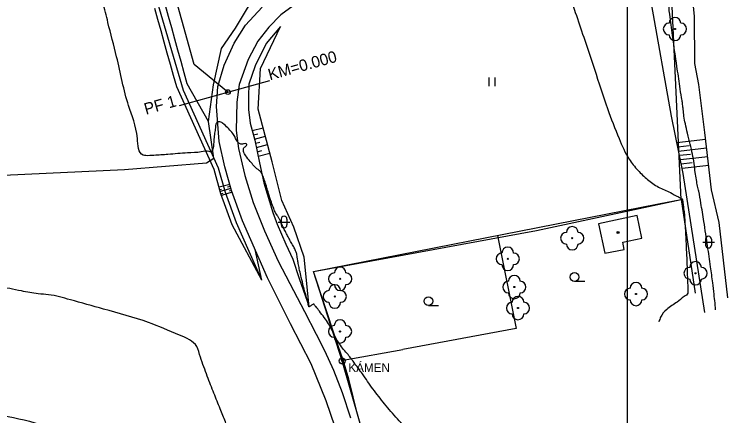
# Model space of a CAD drawing. Extents: x -478102 to -473059, y -1117705 to -1114104.
# Drawn here: x -476287.7 to -476165.9, y -1117155.6 to -1117086.7 of the extents above; entities that cross this region are included whole.
import ezdxf

# ---------------------------------------------------------------- set-up
doc = ezdxf.new("R2010")
doc.units = 0
for name, color, linetype in [('BodoveZnackySloupy', 7, 'Continuous'), ('Budovy', 7, 'Continuous'), ('cestn___p____kop', 7, 'Continuous'), ('cestn___p____kop_n__vrh', 7, 'Continuous'), ('cesty', 7, 'Continuous'), ('DESQ_pomoc', 7, 'Continuous'), ('HladinaVodnihoToku', 7, 'Continuous'), ('ObPÚ', 7, 'Continuous'), ('Ploty', 7, 'Continuous'), ('POLYGONY_SITUACE_PF', 7, 'Continuous'), ('POLYGONY_SITUACE_PF_POPISY', 7, 'Continuous'), ('POLYGONY_SITUACE_PO', 7, 'Continuous'), ('PopisnaZnackaVyhybka', 7, 'Continuous'), ('PopisneZnackyKultura', 7, 'Continuous'), ('PopisObjektu', 7, 'Continuous'), ('RozhraniKultur', 7, 'Continuous'), ('RozhraniVozovky', 7, 'Continuous'), ('Teren_HranaSvahu', 7, 'Continuous'), ('Teren_PataSvahu', 7, 'Continuous'), ('Vrstevnice_hlavni', 7, 'Continuous'), ('Vrstevnice_vedlejsi', 7, 'Continuous'), ('VstupNaPozemek', 7, 'Continuous'), ('VyskoveSrafy', 7, 'Continuous'), ('ZnackyStromu', 7, 'Continuous')]:
    doc.layers.add(name, color=color, linetype=linetype)

msp = doc.modelspace()

# ---------------------------------------------------------------- linework, layer by layer
at = {"layer": 'BodoveZnackySloupy'}
for radius in [0.5, 0.1]:
    msp.add_circle((-476231.32, -1117146.23), radius, dxfattribs=at)
at = {"layer": 'Budovy'}
msp.add_lwpolyline([(-476179.82, -1117125.147), (-476180.599, -1117121.234), (-476187.275, -1117122.701), (-476186.207, -1117127.742), (-476182.873, -1117127.103), (-476183.091, -1117125.822)], close=True, dxfattribs=at)
at = {"layer": 'cestn___p____kop'}
for p, q in [((-476250.632, -1117115.923), (-476252.471, -1117116.401)), ((-476252.362, -1117116.788), (-476252.026, -1117116.7)), ((-476250.433, -1117116.627), (-476252.264, -1117117.134)), ((-476250.534, -1117116.268), (-476250.996, -1117116.397)), ((-476250.345, -1117116.938), (-476250.73, -1117117.053)), ((-476252.157, -1117117.511), (-476251.788, -1117117.406)), ((-476250.225, -1117117.27), (-476252.044, -1117117.829))]:
    msp.add_line(p, q, dxfattribs=at)
at = {"layer": 'cestn___p____kop_n__vrh'}
msp.add_lwpolyline([(-476182.335, -1117180.282), (-476602.335, -1117180.282), (-476602.335, -1116586.282), (-476182.335, -1116586.282)], close=True, dxfattribs=at)
at = {"layer": 'cesty'}
for p, q in [((-476258.59, -1117099.803), (-476264.043, -1117081.125)), ((-476261.133, -1117087.098), (-476261.667, -1117085.17)), ((-476260.599, -1117089.025), (-476261.133, -1117087.098)), ((-476260.064, -1117090.952), (-476260.599, -1117089.025)), ((-476259.53, -1117092.88), (-476260.064, -1117090.952)), ((-476258.996, -1117094.807), (-476259.53, -1117092.88)), ((-476258.461, -1117096.734), (-476258.996, -1117094.807)), ((-476257.927, -1117098.661), (-476258.461, -1117096.734)), ((-476254.26, -1117105.118), (-476257.927, -1117098.661))]:
    msp.add_line(p, q, dxfattribs=at)
for points in [[(-476262.981, -1117087.61), (-476263.521, -1117085.684)], [(-476262.442, -1117089.536), (-476262.981, -1117087.61)], [(-476261.903, -1117091.462), (-476262.442, -1117089.536)], [(-476261.364, -1117093.388), (-476261.903, -1117091.462)], [(-476260.822, -1117095.313), (-476261.364, -1117093.388)], [(-476260.281, -1117097.239), (-476260.822, -1117095.313)], [(-476259.74, -1117099.164), (-476260.281, -1117097.239)], [(-476259.74, -1117099.164), (-476259.74, -1117099.164)]]:
    msp.add_lwpolyline(points, dxfattribs=at)
at = {"layer": 'DESQ_pomoc'}
msp.add_line((-476245.113, -1117132.379), (-476246.288, -1117127.059), dxfattribs=at)
at = {"layer": 'HladinaVodnihoToku'}
msp.add_lwpolyline([(-476165.052, -1117135.383), (-476166.552, -1117122.432), (-476167.831, -1117116.835), (-476168.995, -1117106.978), (-476170.029, -1117098.738), (-476170.701, -1117095.145), (-476170.746, -1117087.056), (-476171.949, -1117074.832), (-476173.391, -1117070.652), (-476173.059, -1117068.741), (-476173.366, -1117065.264), (-476174.142, -1117057.395), (-476175.337, -1117045.193), (-476176.15, -1117036.518), (-476177.362, -1117031.476), (-476176.964, -1117029.141), (-476177.777, -1117025.659), (-476180.222, -1117017.465), (-476181.969, -1117010.204)], dxfattribs=at)
at = {"layer": 'ObPÚ'}
msp.add_lwpolyline([(-476159.5, -1117192.77), (-476224.13, -1117203.13), (-476225.41, -1117191.08), (-476226.67, -1117162.34), (-476231.32, -1117146.23), (-476236.27, -1117130.89), (-476197.93, -1117123.85), (-476173.05, -1117118.52), (-476175.07, -1117075.48), (-476185.89, -1117036.74), (-476189.59, -1117026.33), (-476192, -1117018.92), (-476203.93, -1116985.93)], dxfattribs=at)
at = {"layer": 'Ploty'}
for p, q in [((-476173.05, -1117118.52), (-476170.664, -1117134.589)), ((-476204.648, -1117124.689), (-476201.416, -1117140.657)), ((-476201.416, -1117140.657), (-476220.878, -1117144.236)), ((-476231.16, -1117146.08), (-476220.878, -1117144.236))]:
    msp.add_line(p, q, dxfattribs=at)
for points in [[(-476236.27, -1117130.89), (-476176.96, -1117119.26), (-476173.05, -1117118.52)], [(-476232.38, -1117142.5), (-476236.27, -1117130.89)], [(-476230.16, -1117149.36), (-476231.16, -1117146.08)]]:
    msp.add_lwpolyline(points, dxfattribs=at)
at = {"layer": 'POLYGONY_SITUACE_PF'}
msp.add_lwpolyline([(-476259.271, -1117102.36), (-476250.954, -1117100.054), (-476243.727, -1117098.051)], dxfattribs=at)
at = {"layer": 'POLYGONY_SITUACE_PO'}
msp.add_lwpolyline([(-476250.954, -1117100.054), (-476256.772, -1117095.342), (-476265.518, -1117063.797), (-476268.51, -1117056.912), (-476273.282, -1117051.116), (-476279.465, -1117046.859), (-476286.581, -1117044.469), (-476294.08, -1117044.131), (-476301.427, -1117045.065)], dxfattribs=at)
msp.add_circle((-476250.954, -1117100.054), 0.395, dxfattribs=at)
at = {"layer": 'PopisnaZnackaVyhybka'}
for radius in [0.18, 0.0797]:
    msp.add_circle((-476183.909, -1117124.176), radius, dxfattribs=at)
at = {"layer": 'PopisneZnackyKultura'}
for p, q in [((-476206.051, -1117099.044), (-476206.051, -1117097.544)), ((-476205.051, -1117099.044), (-476205.051, -1117097.544)), ((-476241.815, -1117121.87), (-476241.815, -1117122.87)), ((-476240.815, -1117121.87), (-476240.815, -1117122.87)), ((-476242.315, -1117122.37), (-476240.315, -1117122.37)), ((-476168.864, -1117125.331), (-476168.864, -1117126.331)), ((-476167.864, -1117125.331), (-476167.864, -1117126.331)), ((-476169.364, -1117125.831), (-476167.364, -1117125.831)), ((-476191.384, -1117132.551), (-476189.624, -1117132.551)), ((-476216.498, -1117136.728), (-476214.738, -1117136.728))]:
    msp.add_line(p, q, dxfattribs=at)
for centre in [(-476191.384, -1117131.811), (-476216.498, -1117135.968)]:
    msp.add_circle(centre, 0.75, dxfattribs=at)
for centre, start, end in [((-476241.307, -1117121.862), 0, 180), ((-476241.307, -1117122.862), 180, 0), ((-476168.356, -1117125.324), 0, 180), ((-476168.356, -1117126.324), 180, 0)]:
    msp.add_arc(centre, 0.5, start, end, dxfattribs=at)
at = {"layer": 'RozhraniKultur'}
msp.add_lwpolyline([(-476326.155, -1117118.092), (-476289.536, -1117114.347), (-476268.698, -1117113.377), (-476254.616, -1117112.232), (-476253.368, -1117111.396), (-476254.26, -1117105.118), (-476253.444, -1117098.834), (-476252.052, -1117092.56), (-476249.674, -1117089.102), (-476247.41, -1117085.365), (-476243.552, -1117082.341), (-476239.642, -1117080.005), (-476234.251, -1117077.288), (-476223.428, -1117073.653), (-476215.212, -1117070.499), (-476211.753, -1117068.101), (-476207.257, -1117063.687), (-476203.922, -1117059.007), (-476201.245, -1117053.431), (-476199.908, -1117046.384), (-476198.206, -1117031.932)], dxfattribs=at)
at = {"layer": 'RozhraniVozovky'}
for points in [[(-476232.539, -1117157.584), (-476234.044, -1117153.045), (-476236.653, -1117146.701), (-476240.196, -1117139.821), (-476244.137, -1117131.967), (-476248.439, -1117122.151), (-476250.337, -1117116.965), (-476251.495, -1117112.871), (-476252.444, -1117108.527), (-476252.919, -1117102.558), (-476252.654, -1117099.075), (-476251.576, -1117095.426), (-476249.859, -1117091.68), (-476247.93, -1117088.545), (-476245.077, -1117085.472)], [(-476239.761, -1117085.24), (-476241.85, -1117086.802), (-476243.905, -1117088.925), (-476245.795, -1117091.335), (-476247.443, -1117094.453), (-476248.993, -1117098.742), (-476249.417, -1117101.776), (-476249.514, -1117106.658), (-476249.129, -1117109.728), (-476248.034, -1117114.356), (-476246.613, -1117119.033), (-476244.684, -1117123.906), (-476242.288, -1117129.115), (-476240.331, -1117132.949), (-476237.801, -1117137.737), (-476235.804, -1117141.64), (-476234.344, -1117144.407), (-476232.794, -1117147.784), (-476231.339, -1117151.616), (-476229.905, -1117155.995)], [(-476245.113, -1117132.379), (-476250.203, -1117122.86), (-476252.146, -1117117.551), (-476253.339, -1117113.333), (-476259.74, -1117099.164), (-476259.74, -1117099.164), (-476259.74, -1117099.164)], [(-476245.113, -1117132.379), (-476249.471, -1117122.532), (-476251.384, -1117117.304), (-476252.563, -1117113.138), (-476252.563, -1117113.138), (-476258.59, -1117099.803), (-476258.59, -1117099.803)], [(-476245.113, -1117132.379), (-476250.203, -1117122.86), (-476252.146, -1117117.551), (-476253.339, -1117113.333)], [(-476245.113, -1117132.379), (-476249.471, -1117122.532), (-476251.384, -1117117.304), (-476252.563, -1117113.138)]]:
    msp.add_lwpolyline(points, dxfattribs=at)
at = {"layer": 'Teren_HranaSvahu'}
for p, q in [((-476174.722, -1117104.178), (-476178.08, -1117085.22)), ((-476172.711, -1117114.033), (-476174.722, -1117104.178)), ((-476168.996, -1117137.921), (-476172.711, -1117114.033))]:
    msp.add_line(p, q, dxfattribs=at)
msp.add_lwpolyline([(-476241.907, -1117088.771), (-476244.381, -1117091.697), (-476246.266, -1117095.564), (-476247.357, -1117098.679), (-476247.405, -1117100.757), (-476247.403, -1117103.059), (-476247.148, -1117105.38), (-476246.321, -1117108.303), (-476245.519, -1117112.214), (-476244.755, -1117115.631), (-476243.212, -1117120.707), (-476242.462, -1117122.744), (-476241.012, -1117126.146), (-476239.788, -1117128.744), (-476238.72, -1117132.057), (-476237, -1117136.918)], dxfattribs=at)
at = {"layer": 'Teren_PataSvahu'}
msp.add_lwpolyline([(-476237, -1117136.918), (-476237.832, -1117128.393), (-476239.617, -1117123.274), (-476241.661, -1117118.667), (-476243.331, -1117112.033), (-476245.747, -1117102.973), (-476245.359, -1117095.988), (-476241.907, -1117088.771)], dxfattribs=at)
at = {"layer": 'Vrstevnice_hlavni'}
for points in [[(-476249.493, -1117108.392), (-476249.775, -1117107.699), (-476250.264, -1117106.97), (-476250.958, -1117106.207), (-476251.857, -1117105.408), (-476252.513, -1117105.14), (-476252.925, -1117105.402), (-476253.095, -1117106.195), (-476253.235, -1117107.1), (-476253.347, -1117108.118), (-476253.43, -1117109.248), (-476253.596, -1117109.985), (-476253.847, -1117110.328), (-476254.181, -1117110.278), (-476255.528, -1117110.336), (-476257.887, -1117110.502), (-476261.259, -1117110.776), (-476263.654, -1117110.928), (-476265.074, -1117110.957), (-476265.519, -1117110.863), (-476266.5, -1117108.002), (-476268.017, -1117102.375), (-476270.071, -1117093.98), (-476271.569, -1117088.098), (-476272.511, -1117084.73), (-476272.897, -1117083.874), (-476273.181, -1117083.184), (-476273.365, -1117082.66), (-476273.447, -1117082.301), (-476273.665, -1117081.937), (-476274.021, -1117081.569), (-476274.513, -1117081.196), (-476274.898, -1117080.887), (-476275.174, -1117080.644), (-476275.342, -1117080.466), (-476275.953, -1117078.624), (-476277.006, -1117075.118), (-476278.503, -1117069.948), (-476279.866, -1117064.113), (-476281.094, -1117057.612), (-476282.188, -1117050.447), (-476282.997, -1117045.306), (-476283.52, -1117042.188), (-476283.758, -1117041.094), (-476283.99, -1117040.218), (-476284.216, -1117039.561), (-476284.654, -1117038.684)], [(-476206.652, -1117178.906), (-476206.912, -1117178.348), (-476209.341, -1117173.725), (-476211.536, -1117169.856), (-476213.496, -1117166.739), (-476215.223, -1117164.376), (-476216.372, -1117162.765), (-476216.944, -1117161.906), (-476216.939, -1117161.798), (-476216.948, -1117161.695), (-476216.97, -1117161.597), (-476217.006, -1117161.504), (-476217.035, -1117161.434), (-476217.055, -1117161.387), (-476217.068, -1117161.364), (-476217.869, -1117160.487), (-476219.458, -1117158.755), (-476221.836, -1117156.168), (-476224.025, -1117153.59), (-476226.026, -1117151.021), (-476227.839, -1117148.461), (-476229.316, -1117146.439), (-476230.458, -1117144.956), (-476231.265, -1117144.011), (-476231.967, -1117143.022), (-476232.564, -1117141.99), (-476233.057, -1117140.915), (-476233.666, -1117139.839), (-476234.391, -1117138.762), (-476235.231, -1117137.684), (-476235.806, -1117136.941), (-476236.117, -1117136.531), (-476236.162, -1117136.455), (-476236.279, -1117136.467), (-476236.468, -1117136.566), (-476236.728, -1117136.753), (-476236.903, -1117136.876), (-476236.994, -1117136.936), (-476237.001, -1117136.931), (-476237.008, -1117136.923), (-476237.014, -1117136.912), (-476237.021, -1117136.898), (-476237.036, -1117136.855), (-476237.059, -1117136.783), (-476237.089, -1117136.682), (-476237.266, -1117136.022), (-476237.588, -1117134.805), (-476238.057, -1117133.03), (-476238.423, -1117131.552), (-476238.688, -1117130.371), (-476238.85, -1117129.488), (-476238.979, -1117128.769), (-476239.073, -1117128.213), (-476239.134, -1117127.822), (-476239.32, -1117127.303), (-476239.632, -1117126.656), (-476240.07, -1117125.882), (-476240.487, -1117125.12), (-476240.885, -1117124.371), (-476241.262, -1117123.634), (-476241.579, -1117122.995), (-476241.836, -1117122.453), (-476242.033, -1117122.009), (-476242.251, -1117121.588), (-476242.49, -1117121.19), (-476242.749, -1117120.815), (-476243.08, -1117120.066), (-476243.481, -1117118.944), (-476243.953, -1117117.449), (-476244.291, -1117116.381), (-476244.494, -1117115.74), (-476244.561, -1117115.526), (-476244.665, -1117115.217), (-476244.806, -1117114.813), (-476244.984, -1117114.313), (-476245.236, -1117113.882), (-476245.562, -1117113.52), (-476245.962, -1117113.226), (-476246.483, -1117112.711), (-476247.125, -1117111.974), (-476247.888, -1117111.015), (-476248.249, -1117110.238), (-476248.209, -1117109.642), (-476247.766, -1117109.227), (-476247.681, -1117108.981), (-476247.952, -1117108.903), (-476248.581, -1117108.994), (-476249.094, -1117108.824), (-476249.493, -1117108.392)]]:
    msp.add_spline(points, degree=3, dxfattribs=at)
at = {"layer": 'Vrstevnice_vedlejsi'}
for points in [[(-476361.641, -1116910.017), (-476360.991, -1116911.137), (-476360.552, -1116912.67), (-476360.323, -1116914.616), (-476360.306, -1116916.973), (-476360.308, -1116918.585), (-476360.329, -1116919.449), (-476360.369, -1116919.567), (-476360.386, -1116919.663), (-476360.38, -1116919.738), (-476360.35, -1116919.79), (-476360.486, -1116921.699), (-476360.787, -1116925.464), (-476361.254, -1116931.086), (-476361.67, -1116935.051), (-476362.037, -1116937.36), (-476362.353, -1116938.012), (-476362.549, -1116938.736), (-476362.623, -1116939.532), (-476362.576, -1116940.398), (-476362.264, -1116942.869), (-476361.686, -1116946.945), (-476360.843, -1116952.626), (-476360.093, -1116958.73), (-476359.435, -1116965.256), (-476358.871, -1116972.204), (-476358.36, -1116977.092), (-476357.904, -1116979.919), (-476357.501, -1116980.685), (-476356.57, -1116984.99), (-476355.11, -1116992.835), (-476353.122, -1117004.219), (-476351.571, -1117012.905), (-476350.455, -1117018.893), (-476349.776, -1117022.183), (-476349.504, -1117027.698), (-476349.639, -1117035.437), (-476350.182, -1117045.4), (-476350.307, -1117053.191), (-476350.012, -1117058.811), (-476349.298, -1117062.259), (-476350.091, -1117065.67), (-476352.39, -1117069.042), (-476356.195, -1117072.377), (-476359.92, -1117076.705), (-476363.566, -1117082.026), (-476367.131, -1117088.339), (-476371.33, -1117094.641), (-476376.164, -1117100.933), (-476381.631, -1117107.213), (-476386.474, -1117112.181), (-476390.692, -1117115.834), (-476394.286, -1117118.174), (-476397.491, -1117120.393), (-476400.306, -1117122.492), (-476402.732, -1117124.472), (-476402.928, -1117127.738), (-476400.894, -1117132.291), (-476396.631, -1117138.131), (-476389.647, -1117141.585), (-476379.944, -1117142.653), (-476367.521, -1117141.334), (-476355.525, -1117141.406), (-476343.957, -1117142.868), (-476332.816, -1117145.722), (-476324.482, -1117147.814), (-476318.952, -1117149.144), (-476316.229, -1117149.714), (-476310.745, -1117150.91), (-476302.502, -1117152.733), (-476291.498, -1117155.183), (-476284.107, -1117156.821), (-476280.33, -1117157.647), (-476280.165, -1117157.662), (-476279.816, -1117157.743), (-476279.284, -1117157.891), (-476278.569, -1117158.106), (-476278.072, -1117158.306), (-476277.796, -1117158.489), (-476277.739, -1117158.657), (-476277.684, -1117158.815), (-476277.629, -1117158.963), (-476277.576, -1117159.102), (-476277.523, -1117159.234), (-476277.472, -1117159.361), (-476277.423, -1117159.482), (-476277.379, -1117159.591), (-476277.34, -1117159.689), (-476277.307, -1117159.775), (-476277.275, -1117159.863), (-476277.243, -1117159.954), (-476277.212, -1117160.046), (-476277.173, -1117160.139), (-476277.129, -1117160.233), (-476277.078, -1117160.326), (-476277.04, -1117160.421), (-476277.015, -1117160.516)], [(-476218.662, -1117033.435), (-476218.822, -1117034.635), (-476217.263, -1117036.911), (-476213.986, -1117040.265), (-476208.992, -1117044.695), (-476205.309, -1117047.877), (-476202.938, -1117049.809), (-476201.877, -1117050.493), (-476201.083, -1117050.788), (-476200.555, -1117050.695), (-476200.293, -1117050.212), (-476200.099, -1117049.847), (-476199.974, -1117049.597), (-476199.917, -1117049.464), (-476199.835, -1117049.37), (-476199.726, -1117049.313), (-476199.592, -1117049.295), (-476199.387, -1117049.198), (-476199.112, -1117049.021), (-476198.765, -1117048.765), (-476198.307, -1117048.409), (-476197.736, -1117047.953), (-476197.054, -1117047.397), (-476196.575, -1117047.173), (-476196.299, -1117047.28), (-476196.227, -1117047.719), (-476196.128, -1117048.519), (-476196.001, -1117049.68), (-476195.846, -1117051.202), (-476195.702, -1117052.674), (-476195.567, -1117054.097), (-476195.442, -1117055.471), (-476195.474, -1117056.701), (-476195.663, -1117057.787), (-476196.008, -1117058.731), (-476196.365, -1117059.696), (-476196.731, -1117060.685), (-476197.109, -1117061.695), (-476197.123, -1117063.752), (-476196.775, -1117066.855), (-476196.063, -1117071.005), (-476195.366, -1117074.361), (-476194.682, -1117076.923), (-476194.013, -1117078.692), (-476193.219, -1117080.86), (-476192.302, -1117083.427), (-476191.26, -1117086.392), (-476189.817, -1117090.625), (-476187.973, -1117096.125), (-476185.729, -1117102.894), (-476183.735, -1117108.045), (-476181.992, -1117111.578), (-476180.498, -1117113.494), (-476178.823, -1117115.088), (-476176.965, -1117116.361), (-476174.925, -1117117.312), (-476173.551, -1117118.042), (-476172.843, -1117118.55), (-476172.8, -1117118.837), (-476172.731, -1117119.351), (-476172.637, -1117120.093), (-476172.517, -1117121.062), (-476172.381, -1117123.052), (-476172.229, -1117126.063), (-476172.059, -1117130.096), (-476171.954, -1117132.864), (-476171.913, -1117134.367), (-476171.937, -1117134.606), (-476172.55, -1117135.185), (-476173.752, -1117136.105), (-476175.544, -1117137.365), (-476176.609, -1117138.711), (-476176.875, -1117139.506)], [(-476167.154, -1117137.424), (-476167.161, -1117137.225), (-476167.247, -1117136.247), (-476167.406, -1117134.768), (-476167.64, -1117132.789), (-476168.012, -1117130.045), (-476168.521, -1117126.535), (-476169.167, -1117122.259), (-476169.669, -1117119.115), (-476170.025, -1117117.1), (-476170.236, -1117116.217), (-476170.442, -1117115.129), (-476170.643, -1117113.838), (-476170.838, -1117112.343), (-476171.127, -1117110.728), (-476171.51, -1117108.993), (-476171.987, -1117107.138), (-476172.343, -1117105.532), (-476172.58, -1117104.177), (-476172.697, -1117103.072), (-476172.807, -1117102.176), (-476172.909, -1117101.489), (-476173.004, -1117101.011), (-476173.299, -1117099.062), (-476173.794, -1117095.642), (-476174.488, -1117090.75), (-476174.951, -1117087.207), (-476175.181, -1117085.013), (-476175.18, -1117084.167), (-476175.236, -1117083.188), (-476175.348, -1117082.077), (-476175.517, -1117080.833), (-476175.674, -1117079.86), (-476175.821, -1117079.16), (-476175.956, -1117078.731), (-476176.254, -1117076.34), (-476176.715, -1117071.985), (-476177.338, -1117065.667), (-476177.752, -1117061.381), (-476177.957, -1117059.126), (-476177.954, -1117058.902), (-476177.964, -1117058.642), (-476177.989, -1117058.344), (-476178.028, -1117058.009), (-476178.071, -1117057.621), (-476178.119, -1117057.181), (-476178.171, -1117056.687), (-476178.37, -1117054.109), (-476178.715, -1117049.446), (-476179.207, -1117042.699), (-476179.543, -1117038.092), (-476179.724, -1117035.627)], [(-476223.981, -1117207.237), (-476224.285, -1117206.855), (-476224.501, -1117206.557), (-476224.628, -1117206.343), (-476224.668, -1117206.213), (-476224.801, -1117205.902), (-476225.026, -1117205.411), (-476225.345, -1117204.739), (-476225.578, -1117204.261), (-476225.727, -1117203.975), (-476225.791, -1117203.883), (-476225.875, -1117203.662), (-476225.98, -1117203.311), (-476226.105, -1117202.831), (-476226.229, -1117202.417), (-476226.352, -1117202.067), (-476226.475, -1117201.782), (-476226.572, -1117201.501), (-476226.643, -1117201.224), (-476226.689, -1117200.951), (-476227.057, -1117200.755), (-476227.747, -1117200.637), (-476228.759, -1117200.595), (-476229.446, -1117200.566), (-476229.808, -1117200.548), (-476229.845, -1117200.544), (-476229.875, -1117200.547), (-476229.898, -1117200.559), (-476229.914, -1117200.578), (-476229.923, -1117200.586), (-476229.927, -1117200.583), (-476229.925, -1117200.567), (-476229.926, -1117200.55), (-476229.93, -1117200.533), (-476229.937, -1117200.515), (-476230.309, -1117199.985), (-476231.045, -1117198.942), (-476232.146, -1117197.387), (-476233.138, -1117195.885), (-476234.022, -1117194.438), (-476234.797, -1117193.044), (-476236.35, -1117190.18), (-476238.683, -1117185.847), (-476241.794, -1117180.043), (-476244.171, -1117175.438), (-476245.814, -1117172.033), (-476246.723, -1117169.826), (-476247.372, -1117168.01), (-476247.761, -1117166.585), (-476247.891, -1117165.55), (-476248.161, -1117164.525), (-476248.57, -1117163.508), (-476249.119, -1117162.501), (-476249.598, -1117161.498), (-476250.007, -1117160.498), (-476250.346, -1117159.503), (-476250.69, -1117158.53), (-476251.038, -1117157.58), (-476251.39, -1117156.652), (-476251.803, -1117155.599), (-476252.277, -1117154.423), (-476252.812, -1117153.123), (-476253.36, -1117151.76), (-476253.922, -1117150.336), (-476254.497, -1117148.85), (-476255.085, -1117147.257), (-476255.684, -1117145.558), (-476256.294, -1117143.752), (-476259.267, -1117141.777), (-476264.603, -1117139.631), (-476272.302, -1117137.316), (-476278.025, -1117135.721), (-476281.773, -1117134.847), (-476283.545, -1117134.694), (-476286.438, -1117134.211), (-476290.451, -1117133.398), (-476295.585, -1117132.255), (-476301.704, -1117130.929), (-476308.808, -1117129.42), (-476316.898, -1117127.729), (-476324.767, -1117125.966), (-476332.416, -1117124.134), (-476339.844, -1117122.232), (-476344.627, -1117120.838), (-476346.763, -1117119.952), (-476346.254, -1117119.574), (-476345.231, -1117118.402), (-476343.693, -1117116.434), (-476341.642, -1117113.672), (-476338.379, -1117110.142), (-476333.906, -1117105.844), (-476328.223, -1117100.779), (-476323.405, -1117096.497), (-476319.453, -1117093.001), (-476316.366, -1117090.289), (-476314.122, -1117087.639), (-476312.721, -1117085.051)]]:
    msp.add_spline(points, degree=3, dxfattribs=at)
at = {"layer": 'VstupNaPozemek'}
for p, q in [((-476231.16, -1117146.08), (-476232.38, -1117142.5)), ((-476228.67, -1117155.4), (-476230.16, -1117149.36))]:
    msp.add_line(p, q, dxfattribs=at)
at = {"layer": 'VyskoveSrafy'}
for p, q in [((-476246.78, -1117106.68), (-476244.893, -1117106.177)), ((-476246.576, -1117107.402), (-476245.825, -1117107.202)), ((-476246.372, -1117108.124), (-476244.506, -1117107.626)), ((-476246.208, -1117108.856), (-476245.45, -1117108.654)), ((-476173.799, -1117108.703), (-476168.86, -1117108.119)), ((-476246.057, -1117109.592), (-476244.12, -1117109.075)), ((-476173.648, -1117109.44), (-476171.698, -1117109.21)), ((-476173.498, -1117110.178), (-476168.684, -1117109.609)), ((-476245.906, -1117110.328), (-476245.114, -1117110.117)), ((-476245.755, -1117111.064), (-476243.733, -1117110.525)), ((-476173.347, -1117110.915), (-476171.447, -1117110.691)), ((-476173.197, -1117111.652), (-476168.508, -1117111.099)), ((-476173.046, -1117112.39), (-476171.196, -1117112.171)), ((-476172.896, -1117113.127), (-476168.332, -1117112.588))]:
    msp.add_line(p, q, dxfattribs=at)
at = {"layer": 'ZnackyStromu'}
for centre in [(-476174.131, -1117089.228), (-476191.781, -1117125.147), (-476202.859, -1117128.689), (-476170.593, -1117131.169), (-476231.66, -1117132.12), (-476201.736, -1117133.536), (-476232.59, -1117135.153), (-476180.824, -1117134.734), (-476201.104, -1117137.144), (-476231.678, -1117141.157)]:
    msp.add_circle(centre, 0.1, dxfattribs=at)
for centre, start, end in [((-476174.131, -1117088.228), 0, 180), ((-476175.131, -1117089.228), 90, 270), ((-476173.131, -1117089.228), 270, 90), ((-476174.131, -1117090.228), 180, 0), ((-476191.781, -1117124.147), 0, 180), ((-476192.781, -1117125.147), 90, 270), ((-476190.781, -1117125.147), 270, 90), ((-476202.859, -1117127.689), 0, 180), ((-476191.781, -1117126.147), 180, 0), ((-476203.859, -1117128.689), 90, 270), ((-476201.859, -1117128.689), 270, 90), ((-476170.593, -1117130.169), 0, 180), ((-476231.66, -1117131.12), 0, 180), ((-476202.859, -1117129.689), 180, 0), ((-476171.593, -1117131.169), 90, 270), ((-476169.593, -1117131.169), 270, 90), ((-476232.66, -1117132.12), 90, 270), ((-476230.66, -1117132.12), 270, 90), ((-476201.736, -1117132.536), 0, 180), ((-476202.736, -1117133.536), 90, 270), ((-476200.736, -1117133.536), 270, 90), ((-476180.824, -1117133.734), 0, 180), ((-476170.593, -1117132.169), 180, 0), ((-476233.59, -1117135.153), 90, 270), ((-476232.59, -1117134.153), 0, 180), ((-476231.66, -1117133.12), 180, 0), ((-476231.59, -1117135.153), 270, 90), ((-476181.824, -1117134.734), 90, 270), ((-476179.824, -1117134.734), 270, 90), ((-476201.736, -1117134.536), 180, 0), ((-476201.104, -1117136.144), 0, 180), ((-476232.59, -1117136.153), 180, 0), ((-476202.104, -1117137.144), 90, 270), ((-476200.104, -1117137.144), 270, 90), ((-476180.824, -1117135.734), 180, 0), ((-476201.104, -1117138.144), 180, 0), ((-476232.678, -1117141.157), 90, 270), ((-476231.678, -1117140.157), 0, 180), ((-476230.678, -1117141.157), 270, 90), ((-476231.678, -1117142.157), 180, 0)]:
    msp.add_arc(centre, 1, start, end, dxfattribs=at)

# ---------------------------------------------------------------- texts
at = {"layer": 'POLYGONY_SITUACE_PF_POPISY'}
for s, p in [('KM=0.000', (-476243.739, -1117098.054)), ('PF 1', (-476265.038, -1117103.959))]:
    msp.add_text(s, height=1.9765, rotation=15.49633, dxfattribs=at).set_placement(p)
at = {"layer": 'PopisObjektu'}
msp.add_text('KÁMEN', height=1.5, dxfattribs=at).set_placement((-476230.251, -1117148.116))

doc.saveas('drawing.dxf')
